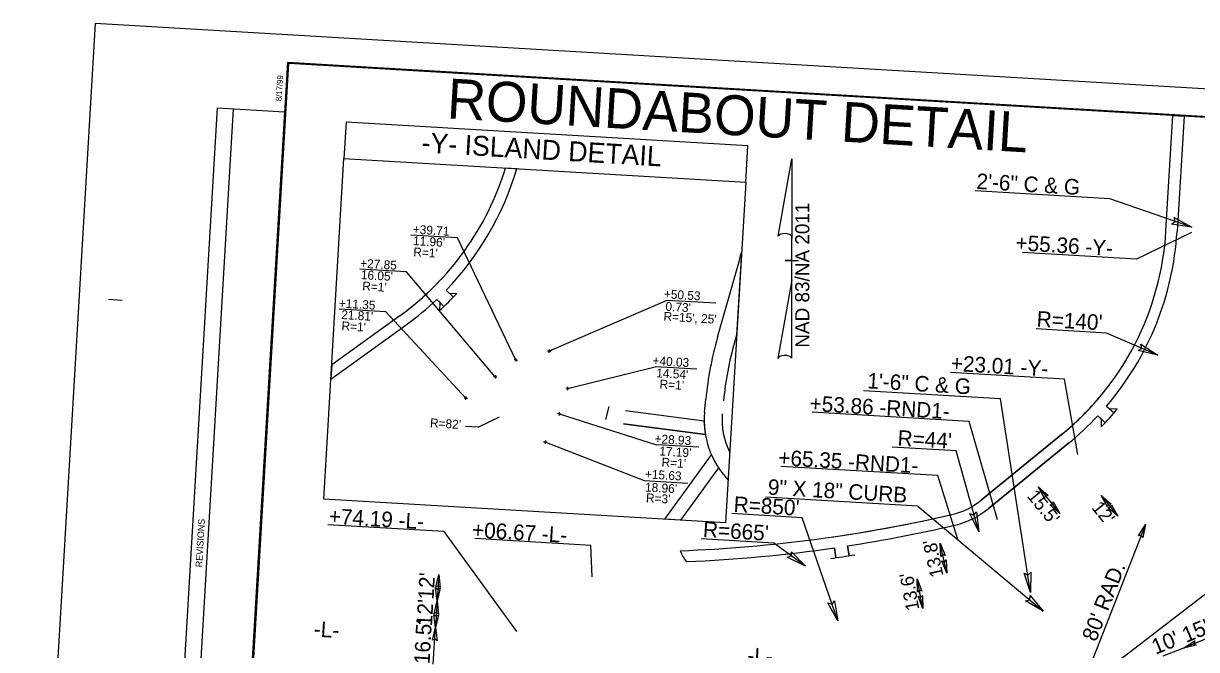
# Model space of a CAD drawing. Extents: x 2011491 to 2012372, y 444688 to 445287.
# Drawn here: x 2011491 to 2012020, y 445005 to 445287 of the extents above; entities that cross this region are included whole.
import ezdxf

# ---------------------------------------------------------------- set-up
doc = ezdxf.new("R2010")
doc.units = 0
for name, color, linetype in [('Old_Level_1', 7, 'Continuous'), ('Old_Level_10', 7, 'Continuous'), ('Prop Conc 4in Sidewalk', 7, 'Continuous'), ('Prop Dimension', 7, 'Continuous'), ('Prop Dimension Text', 7, 'Continuous'), ('Prop North Arrow NAD83 for Plan Sheets CELL', 7, 'Continuous'), ('Prop Shade Medium', 7, 'Continuous'), ('Prop Terminator CELL', 7, 'Continuous'), ('Sheet Block Revision CELL', 7, 'Continuous'), ('Sheet Clip Boundary CELL', 7, 'Continuous'), ('Sheet Plan And Profile CELL', 7, 'Continuous'), ('Sheet Plot Border Outside CELL', 7, 'Continuous')]:
    doc.layers.add(name, color=color, linetype=linetype)

msp = doc.modelspace()

# ---------------------------------------------------------------- linework, layer by layer
at = {"layer": 'Old_Level_1'}
for points in [[(2011635.49, 445226.57), (2011816.54, 445215.89), (2011817.5, 445232.22), (2011636.45, 445242.89)], [(2011635.49, 445226.57), (2011816.54, 445215.89), (2011807.37, 445062.4), (2011626.44, 445073.06)]]:
    msp.add_lwpolyline(points, close=True, dxfattribs=at)
at = {"layer": 'Prop Conc 4in Sidewalk'}
for p, q in [((2011797.85, 445108.23), (2011762.36, 445112.91)), ((2011798.4, 445102.11), (2011761.41, 445106.99)), ((2011922.7, 445072.6), (2011958.89, 445102.11)), ((2011925.87, 445068.72), (2011962.05, 445098.24)), ((2011862.42, 445051.98), (2011862.7, 445050.13))]:
    msp.add_line(p, q, dxfattribs=at)
for centre, radius, start, end in [((2011585.37, 445259.83), 128.5, 305.8308, 316.1784), ((2011585.37, 445259.83), 133.5, 305.8308, 313.5561), ((2011877.67, 445201.69), 128.5, 309.2044, 319.552), ((2011877.67, 445201.69), 133.5, 309.2044, 316.9297), ((2011902.16, 445097.78), 32.5, 283.0186, 309.2044), ((2011762.27, 445702.82), 653.5, 278.22713, 283.01865), ((2011902.16, 445097.78), 37.5, 283.0186, 309.2044), ((2011762.27, 445702.82), 658.5, 278.74762, 283.01865)]:
    msp.add_arc(centre, radius, start, end, dxfattribs=at)
at = {"layer": 'Prop Dimension'}
for p, q in [((2011980.67, 445208.37), (2011920, 445211.95)), ((2012017.55, 445195.6), (2011980.67, 445208.37)), ((2011686.65, 445190.81), (2011665.69, 445192.05)), ((2011712.96, 445135.76), (2011686.65, 445190.81)), ((2011992.66, 445181.17), (2011941.29, 445184.2)), ((2011663.65, 445175.45), (2011642.69, 445176.69)), ((2011703.67, 445128.17), (2011663.65, 445175.45)), ((2011781.02, 445162.64), (2011727.89, 445139.68)), ((2011803.09, 445161.34), (2011781.02, 445162.64)), ((2011654.3, 445157.48), (2011633.34, 445158.72)), ((2011690.34, 445118.54), (2011654.3, 445157.48)), ((2011979.12, 445147.89), (2011947.42, 445149.76)), ((2011736.16, 445122.95), (2011775.7, 445132.73)), ((2011794.54, 445131.62), (2011775.7, 445132.73)), ((2011960.13, 445127.05), (2011908.76, 445130.08)), ((2011931.4, 445118.19), (2011869.69, 445121.83)), ((2011944.94, 445030.96), (2011931.4, 445118.19)), ((2011732.46, 445111.52), (2011776.38, 445097.54)), ((2011917.29, 445108.08), (2011846.5, 445112.25)), ((2011695.92, 445105.44), (2011705.61, 445110.08)), ((2011695.92, 445105.44), (2011690.26, 445105.78)), ((2011770.91, 445081.3), (2011726.22, 445098.71)), ((2011795.44, 445096.41), (2011776.38, 445097.54)), ((2011911.37, 445094.78), (2011882.54, 445096.48)), ((2011921.53, 445058.27), (2011911.37, 445094.78)), ((2011903.18, 445083.63), (2011832.39, 445087.81)), ((2011790.48, 445080.15), (2011770.91, 445081.3)), ((2011948.28, 445078.62), (2011958.07, 445066.61)), ((2011976.67, 445074.68), (2011984.25, 445065.38)), ((2011894.06, 445069.95), (2011825.51, 445073.99)), ((2011894.06, 445069.95), (2011950.61, 445022.61)), ((2011841.96, 445064.66), (2011810.26, 445066.53)), ((2011858.06, 445018.23), (2011841.96, 445064.66)), ((2011680.51, 445058.41), (2011628.18, 445061.49)), ((2011680.51, 445058.41), (2011713.28, 445013.31)), ((2011996.65, 445061.65), (2011967.46, 444987.16)), ((2011746.74, 445052.19), (2011694.42, 445055.28)), ((2011829.18, 445053.25), (2011796.42, 445055.18)), ((2011843.5, 445042.8), (2011829.18, 445053.25)), ((2011907.12, 445039.69), (2011904.18, 445053.14)), ((2011747.28, 445037.98), (2011746.74, 445052.19)), ((2011678.18, 445039.14), (2011677.45, 445027.16)), ((2011896.29, 445023.69), (2011893.8, 445037.08)), ((2011903.98, 444938.48), (2012030.95, 445035.85)), ((2011677.45, 445027.16), (2011676.73, 445015.19)), ((2011675.75, 444998.63), (2011676.73, 445015.19)), ((2012027.71, 445011.57), (2012013.8, 445005.94)), ((2012013.8, 445005.94), (2012004.54, 445002.19))]:
    msp.add_line(p, q, dxfattribs=at)
at = {"layer": 'Prop Dimension Text'}
for p, q in [((2012017.41, 445193.27), (2011992.66, 445181.17)), ((2012002.27, 445137.87), (2011979.12, 445147.89)), ((2011727.89, 445139.68), (2011727.14, 445139.73)), ((2011727.93, 445140.43), (2011727.84, 445138.93)), ((2011727.89, 445139.68), (2011728.64, 445139.64)), ((2011712.96, 445135.76), (2011712.22, 445135.81)), ((2011713.01, 445136.51), (2011712.92, 445135.01)), ((2011712.96, 445135.76), (2011713.71, 445135.72)), ((2011703.67, 445128.17), (2011702.92, 445128.22)), ((2011703.71, 445128.92), (2011703.63, 445127.42)), ((2011703.67, 445128.17), (2011704.42, 445128.13)), ((2011966.16, 445093.2), (2011960.13, 445127.05)), ((2011736.16, 445122.95), (2011735.42, 445122.99)), ((2011736.21, 445123.69), (2011736.12, 445122.2)), ((2011736.16, 445122.95), (2011736.91, 445122.9)), ((2011690.34, 445118.54), (2011689.59, 445118.59)), ((2011690.38, 445119.29), (2011690.3, 445117.79)), ((2011690.34, 445118.54), (2011691.09, 445118.5)), ((2011732.46, 445111.52), (2011731.72, 445111.56)), ((2011732.51, 445112.26), (2011732.42, 445110.77)), ((2011732.46, 445111.52), (2011733.21, 445111.47)), ((2011929.97, 445063.69), (2011917.29, 445108.08)), ((2011726.22, 445098.71), (2011725.47, 445098.75)), ((2011726.26, 445099.46), (2011726.17, 445097.96)), ((2011726.22, 445098.71), (2011726.97, 445098.67)), ((2011912.07, 445054.91), (2011903.18, 445083.63))]:
    msp.add_line(p, q, dxfattribs=at)
at = {"layer": 'Prop North Arrow NAD83 for Plan Sheets CELL'}
for p, q in [((2011831.13, 445191.62), (2011837.29, 445226.38)), ((2011837.33, 445226.38), (2011837.29, 445226.38)), ((2011837.33, 445226.38), (2011837.29, 445226.38)), ((2011837.33, 445226.38), (2011837.32, 445190.53)), ((2011837.32, 445171.93), (2011837.32, 445191.58)), ((2011837.32, 445190.53), (2011837.32, 445191.55)), ((2011834.32, 445180.63), (2011834.28, 445180.63)), ((2011836.98, 445180.63), (2011834.32, 445180.63)), ((2011834.36, 445180.63), (2011840.36, 445180.63)), ((2011837.32, 445171.93), (2011831.05, 445136.5)), ((2011837.35, 445136.65), (2011837.32, 445171.93))]:
    msp.add_line(p, q, dxfattribs=at)
for centre, start_param, end_param in [((2011834.24, 445191.25), 0.216388, 2.908219), ((2011834.23, 445136.37), 0.201328, 3.141593)]:
    msp.add_ellipse(centre, major_axis=(3.17, -0.02), ratio=0.461098, start_param=start_param, end_param=end_param, dxfattribs=at)
at = {"layer": 'Prop Shade Medium'}
for p, q in [((2012005.93, 445193.96), (2012009.07, 445246.03)), ((2012009.07, 445246.03), (2012014.06, 445245.74)), ((2012014.06, 445245.74), (2012010.93, 445193.66)), ((2011713.39, 445221.97), (2011708.26, 445222.28)), ((2011814.65, 445184.27), (2011812.42, 445146.97)), ((2011803.82, 445145.99), (2011812.39, 445175.96)), ((2011684.78, 445164.11), (2011681.61, 445167.31)), ((2011683.02, 445165.89), (2011686.33, 445165.75)), ((2011678.77, 445161.66), (2011677.36, 445163.08)), ((2011677.36, 445163.08), (2011680.53, 445159.88)), ((2011678.62, 445158.1), (2011678.77, 445161.65)), ((2011660.59, 445155.65), (2011630.01, 445133.56)), ((2011629.63, 445127.12), (2011663.52, 445151.59)), ((2011812.42, 445146.97), (2011811.52, 445143.79)), ((2011630.01, 445133.56), (2011629.63, 445127.12)), ((2011798.02, 445112.28), (2011798.58, 445118.16)), ((2011754.89, 445114.78), (2011753.33, 445108.99)), ((2011754.89, 445114.78), (2011753.33, 445108.99)), ((2011797.85, 445108.23), (2011762.36, 445112.91)), ((2011980.68, 445113.65), (2011979.18, 445114.99)), ((2011979.18, 445114.99), (2011982.54, 445111.99)), ((2011983.99, 445113.71), (2011980.67, 445113.65)), ((2011761.41, 445106.99), (2011798.4, 445102.11)), ((2011798.4, 445102.11), (2011797.85, 445108.23)), ((2011975.19, 445110.52), (2011976.68, 445109.18)), ((2011978.54, 445107.51), (2011975.19, 445110.52)), ((2011976.68, 445109.18), (2011976.74, 445105.62)), ((2011958.89, 445102.11), (2011922.7, 445072.6)), ((2011922.7, 445072.6), (2011958.89, 445102.11)), ((2011925.87, 445068.72), (2011962.05, 445098.24)), ((2011962.05, 445098.24), (2011925.87, 445068.72)), ((2011780.05, 445064.01), (2011801.1, 445093.03)), ((2011804.27, 445087.18), (2011787.16, 445063.59)), ((2011787.16, 445063.59), (2011780.05, 445064.01)), ((2011856.5, 445051.1), (2011857.14, 445046.64)), ((2011856.78, 445049.18), (2011856.5, 445051.1)), ((2011857.2, 445046.65), (2011856.82, 445049.19)), ((2011863.1, 445047.53), (2011862.42, 445051.98)), ((2011862.42, 445051.98), (2011862.7, 445050.13)), ((2011862.7, 445050.13), (2011863.11, 445047.53))]:
    msp.add_line(p, q, dxfattribs=at)
for centre, radius, start, end in [((2011585.37, 445259.83), 128.5, 305.8308, 343.0084), ((2011585.37, 445259.83), 133.5, 316.1277, 343.5277), ((2011877.67, 445201.69), 128.5, 309.2044, 356.5533), ((2011877.67, 445201.69), 128.5, 309.2044, 356.5533), ((2011877.67, 445201.69), 133.5, 319.5013, 356.5533), ((2011877.67, 445201.69), 133.5, 319.5013, 356.5533), ((2011479.7, 445271.02), 346, 344.0535, 345.4788), ((2011585.37, 445259.83), 128.5, 305.8308, 316.1784), ((2011585.37, 445259.83), 138, 312.5102, 317.0216), ((2011585.37, 445259.83), 133.5, 305.8308, 313.5561), ((2011585.37, 445259.83), 133.5, 305.8308, 313.5561), ((2011951.9, 445103.68), 154, 164.0535, 174.6031), ((2011951.9, 445103.68), 146, 164.0535, 174.6031), ((2011836.85, 445108.61), 39, 174.6031, 223.4388), ((2011836.85, 445108.61), 31, 174.6031, 207.231), ((2011877.67, 445201.69), 138, 315.8838, 320.3952), ((2011877.67, 445201.69), 133.5, 309.2044, 316.9297), ((2011877.67, 445201.69), 133.5, 309.2044, 316.9297), ((2011902.16, 445097.78), 32.5, 283.0186, 309.2044), ((2011902.16, 445097.78), 32.5, 283.0186, 309.2044), ((2011762.27, 445702.82), 653.5, 272.17018, 283.01865), ((2011762.27, 445702.82), 653.5, 278.22713, 283.01865), ((2011902.16, 445097.78), 37.5, 283.0186, 309.2044), ((2011902.16, 445097.78), 37.5, 283.0186, 309.2044), ((2011762.27, 445702.82), 658.5, 278.74762, 283.01865), ((2011762.27, 445702.82), 658.5, 278.74762, 283.01865), ((2011799.36, 445053.88), 13, 198.3383, 223.6709), ((2011762.27, 445702.82), 658.5, 272.40941, 278.22713), ((2011762.27, 445702.82), 663, 278.01181, 278.9762)]:
    msp.add_arc(centre, radius, start, end, dxfattribs=at)
at = {"layer": 'Prop Terminator CELL'}
for points in [[(2012009.56, 445200.01), (2012017.55, 445195.6), (2012008.48, 445197.05), (2012010.09, 445198.18)], [(2011994.63, 445142.86), (2012002.27, 445137.87), (2011993.33, 445139.99), (2011995.02, 445141)], [(2011951.19, 445073.45), (2011948.28, 445078.62), (2011952.8, 445074.72), (2011951.52, 445074.64)], [(2011979.58, 445069.51), (2011976.67, 445074.68), (2011981.19, 445070.78), (2011979.91, 445070.7)], [(2011955.15, 445071.78), (2011958.07, 445066.61), (2011953.55, 445070.51), (2011954.83, 445070.59)], [(2011981.34, 445070.55), (2011984.25, 445065.38), (2011979.73, 445069.28), (2011981.01, 445069.36)], [(2011920.61, 445067.36), (2011921.53, 445058.27), (2011917.56, 445066.56), (2011919.41, 445065.88)], [(2011993.58, 445056.57), (2011996.65, 445061.65), (2011995.47, 445055.79), (2011994.78, 445056.87)], [(2011904.45, 445047.21), (2011904.18, 445053.14), (2011906.45, 445047.61), (2011905.28, 445048.12)], [(2011837.15, 445049.36), (2011843.5, 445042.8), (2011835.25, 445046.84), (2011837.12, 445047.46)], [(2011906.86, 445045.62), (2011907.12, 445039.69), (2011904.85, 445045.21), (2011906.02, 445044.7)], [(2011676.82, 445033.36), (2011678.18, 445039.14), (2011678.86, 445033.21), (2011677.87, 445034.02)], [(2011945.09, 445040.09), (2011944.94, 445030.96), (2011941.97, 445039.66), (2011943.72, 445038.76)], [(2011678.81, 445032.94), (2011677.45, 445027.16), (2011676.77, 445033.1), (2011677.76, 445032.29)], [(2011893.88, 445031.14), (2011893.8, 445037.08), (2011895.9, 445031.49), (2011894.74, 445032.03)], [(2011676.09, 445021.39), (2011677.45, 445027.16), (2011678.14, 445021.23), (2011677.14, 445022.04)], [(2011856.57, 445027.24), (2011858.06, 445018.23), (2011853.58, 445026.25), (2011855.47, 445025.69)], [(2011896.21, 445029.63), (2011896.29, 445023.69), (2011894.19, 445029.28), (2011895.35, 445028.74)], [(2011944.7, 445029.57), (2011950.61, 445022.61), (2011942.64, 445027.19), (2011944.55, 445027.68)], [(2011678.09, 445020.96), (2011676.73, 445015.19), (2011676.05, 445021.12), (2011677.04, 445020.31)], [(2011675.38, 445009.41), (2011676.73, 445015.19), (2011677.42, 445009.25), (2011676.43, 445010.06)], [(2012019.6, 445007.2), (2012013.8, 445005.94), (2012018.87, 445009.11), (2012018.56, 445007.87)]]:
    msp.add_lwpolyline(points, close=True, dxfattribs=at)
at = {"layer": 'Sheet Block Revision CELL'}
msp.add_line((2011562.49, 444854.41), (2011585.75, 445249.04), dxfattribs=at)
msp.add_lwpolyline([(2011555.23, 444854.83), (2011578.49, 445249.47), (2011608.71, 445247.69), (2011585.45, 444853.05)], close=True, dxfattribs=at)
at = {"layer": 'Sheet Clip Boundary CELL'}
for points in [[(2012353.36, 445134.84), (2012253.51, 445140.73), (2012256.91, 445198.29), (2012157.05, 445204.18), (2012159.02, 445237.47), (2011610.02, 445269.83), (2011579.13, 444745.74), (2012327.83, 444701.6)], [(2011579.79, 444746.22), (2011610.64, 445269.52), (2012158.83, 445237.2), (2012156.87, 445204), (2012256.73, 445198.11), (2012253.34, 445140.51), (2012353.28, 445134.62), (2012327.76, 444701.71)]]:
    msp.add_lwpolyline(points, close=True, dxfattribs=at)
at = {"layer": 'Sheet Plan And Profile CELL'}
msp.add_line((2011529.35, 445163.14), (2011535.59, 445162.77), dxfattribs=at)
msp.add_lwpolyline([(2012358.72, 445225.69), (2011610.02, 445269.83), (2011579.13, 444745.74), (2012327.83, 444701.6)], close=True, dxfattribs=at)
at = {"layer": 'Sheet Plot Border Outside CELL'}
msp.add_lwpolyline([(2011491.04, 444738.41), (2012339.57, 444688.39), (2012371.93, 445237.44), (2011523.41, 445287.46)], close=True, dxfattribs=at)

# ---------------------------------------------------------------- texts
at = {"layer": 'Old_Level_10'}
for s, p in [('+39.71', (2011666.42, 445192.74)), ("11.96'", (2011666.5, 445187.58)), ("R=1'", (2011666.64, 445182.52)), ('+27.85', (2011642.71, 445177.42)), ("16.05'", (2011643.02, 445172.25)), ("R=1'", (2011643.64, 445167.16)), ('+50.53', (2011779.57, 445163.58)), ('+11.35', (2011633.07, 445159.42)), ("0.73'", (2011780.27, 445157.96)), ("21.81'", (2011634.15, 445154.25)), ("R=15', 25'", (2011779.41, 445153.5)), ("R=1'", (2011634.29, 445149.19)), ('+40.03', (2011774.46, 445133.53)), ("14.54'", (2011776.13, 445127.99)), ("R=1'", (2011777.62, 445122.95)), ("R=82'", (2011674.17, 445105.49)), ('+28.93', (2011775.36, 445098.33)), ("17.19'", (2011777.51, 445092.76)), ("R=1'", (2011778.52, 445087.74)), ('+15.63', (2011771.03, 445082.4)), ("18.96'", (2011771.07, 445076.53)), ("R=3'", (2011771.49, 445071.69))]:
    msp.add_text(s, height=4, rotation=356.6264, dxfattribs=at).set_placement(p)
at = {"layer": 'Prop Dimension'}
for s, height, p in [('ROUNDABOUT DETAIL', 18, (2011681.63, 445244.73)), ('-Y- ISLAND DETAIL', 9, (2011670.28, 445229.37)), ('-L-', 7, (2011621.74, 445011.1)), ('-L-', 7, (2011817.14, 444999.27))]:
    msp.add_text(s, height=height, rotation=356.6264, dxfattribs=at).set_placement(p)
at = {"layer": 'Prop Dimension Text'}
for s, height, rotation, p in [('2\'-6" C & G', 7, 356.6264, (2011920.37, 445212.91)), ('+55.36 -Y-', 7, 356.6264, (2011937.97, 445185.25)), ("R=140'", 7, 356.6264, (2011947.51, 445150.86)), ('+23.01 -Y-', 7, 356.6264, (2011908.79, 445130.93)), ('1\'-6" C & G', 7, 356.6264, (2011871.18, 445123.01)), ('+53.86 -RND1-', 7, 356.6264, (2011845.18, 445112.82)), ("R=44'", 7, 356.6264, (2011884.83, 445097.2)), ('+65.35 -RND1-', 7, 356.6264, (2011831.07, 445088.38)), ('9" X 18" CURB ', 7, 356.6264, (2011826.36, 445075.1)), ("R=850'", 7, 356.6264, (2011810.96, 445067.34)), ("15.5'", 6, 309.2044, (2011943.04, 445074.26)), ("12'", 6, 309.2044, (2011972.11, 445069.1)), ('+74.19 -L-', 7, 356.6264, (2011628.48, 445061.96)), ('+06.67 -L-', 7, 356.6264, (2011693.04, 445055.85)), ("R=665'", 7, 356.6264, (2011797.12, 445055.99)), ("13.8'", 6, 102.3217, (2011905.73, 445038.55)), ("80' RAD.", 7, 68.6045, (2011974.34, 445008.4)), ("12'", 7, 87.057, (2011675.89, 445027.56)), ("13.6'", 6, 100.5597, (2011894.83, 445023.4)), ("12'", 7, 87.057, (2011675.16, 445015.59)), ("16.5'", 7, 87.057, (2011674.06, 444998.54)), ("15'", 7, 22.5868, (2012015.05, 445008.19)), ("10'", 7, 22.5868, (2012001.27, 445002.84))]:
    msp.add_text(s, height=height, rotation=rotation, dxfattribs=at).set_placement(p)
at = {"layer": 'Prop North Arrow NAD83 for Plan Sheets CELL'}
msp.add_text('NAD 83/NA 2011', height=6.375, rotation=89.9922, dxfattribs=at).set_placement((2011845.2, 445141.31))
at = {"layer": 'Sheet Block Revision CELL'}
msp.add_text('REVISIONS', height=3, rotation=86.6264, dxfattribs=at).set_placement((2011571.54, 445042.27))
at = {"layer": 'Sheet Plan And Profile CELL'}
msp.add_text('8/17/99', height=2.625, rotation=86.6264, dxfattribs=at).set_placement((2011607.36, 445252.35))

doc.saveas('drawing.dxf')
